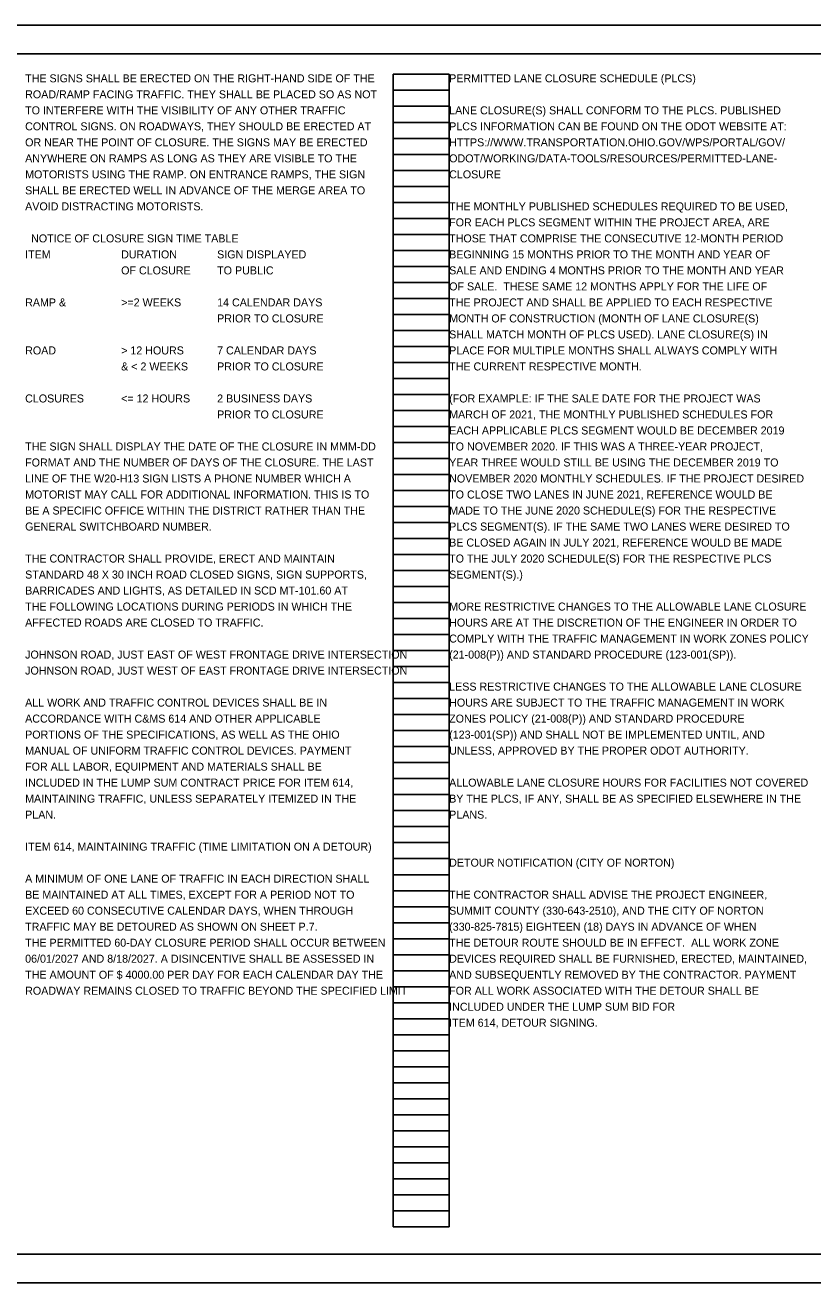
# Model space of a CAD drawing. Extents: x -9.9 to 34, y 0 to 22.
# Drawn here: x 9.82 to 23.6, y 0 to 22 of the extents above; entities that cross this region are included whole.
import ezdxf

# ---------------------------------------------------------------- set-up
doc = ezdxf.new("R2010")
doc.units = 0
for name, color, linetype in [('SH_Border', 7, 'Continuous'), ('SH_Cut_Line', 7, 'Continuous'), ('SH_Data', 7, 'Continuous'), ('SH_Text', 7, 'Continuous')]:
    doc.layers.add(name, color=color, linetype=linetype)

msp = doc.modelspace()

# ---------------------------------------------------------------- linework, layer by layer
at = {"layer": 'SH_Border'}
msp.add_lwpolyline([(1.5, 21.5), (33.5, 21.5), (33.5, 0.5), (1.5, 0.5)], close=True, dxfattribs=at)
at = {"layer": 'SH_Cut_Line'}
msp.add_lwpolyline([(0, 0), (34, 0), (34, 22), (0, 22)], close=True, dxfattribs=at)
at = {"layer": 'SH_Data'}
for p, q in [((16.26, 0.98), (16.26, 21.14)), ((16.26, 21.14), (17.24, 21.14)), ((17.24, 0.98), (17.24, 21.14)), ((16.26, 20.86), (17.24, 20.86)), ((16.26, 20.58), (17.24, 20.58)), ((16.26, 20.3), (17.24, 20.3)), ((16.26, 20.02), (17.24, 20.02)), ((16.26, 19.74), (17.24, 19.74)), ((16.26, 19.46), (17.24, 19.46)), ((16.26, 19.18), (17.24, 19.18)), ((16.26, 18.9), (17.24, 18.9)), ((16.26, 18.62), (17.24, 18.62)), ((16.26, 18.34), (17.24, 18.34)), ((16.26, 18.06), (17.24, 18.06)), ((16.26, 17.78), (17.24, 17.78)), ((16.26, 17.5), (17.24, 17.5)), ((16.26, 17.22), (17.24, 17.22)), ((16.26, 16.94), (17.24, 16.94)), ((16.26, 16.66), (17.24, 16.66)), ((16.26, 16.38), (17.24, 16.38)), ((16.26, 16.1), (17.24, 16.1)), ((16.26, 15.82), (17.24, 15.82)), ((16.26, 15.54), (17.24, 15.54)), ((16.26, 15.26), (17.24, 15.26)), ((16.26, 14.98), (17.24, 14.98)), ((16.26, 14.7), (17.24, 14.7)), ((16.26, 14.42), (17.24, 14.42)), ((16.26, 14.14), (17.24, 14.14)), ((16.26, 13.86), (17.24, 13.86)), ((16.26, 13.58), (17.24, 13.58)), ((16.26, 13.3), (17.24, 13.3)), ((16.26, 13.02), (17.24, 13.02)), ((16.26, 12.74), (17.24, 12.74)), ((16.26, 12.46), (17.24, 12.46)), ((16.26, 12.18), (17.24, 12.18)), ((16.26, 11.9), (17.24, 11.9)), ((16.26, 11.62), (17.24, 11.62)), ((16.26, 11.34), (17.24, 11.34)), ((16.26, 11.06), (17.24, 11.06)), ((16.26, 10.78), (17.24, 10.78)), ((16.26, 10.5), (17.24, 10.5)), ((16.26, 10.22), (17.24, 10.22)), ((16.26, 9.94), (17.24, 9.94)), ((16.26, 9.66), (17.24, 9.66)), ((16.26, 9.38), (17.24, 9.38)), ((16.26, 9.1), (17.24, 9.1)), ((16.26, 8.82), (17.24, 8.82)), ((16.26, 8.54), (17.24, 8.54)), ((16.26, 8.26), (17.24, 8.26)), ((16.26, 7.98), (17.24, 7.98)), ((16.26, 7.7), (17.24, 7.7)), ((16.26, 7.42), (17.24, 7.42)), ((16.26, 7.14), (17.24, 7.14)), ((16.26, 6.86), (17.24, 6.86)), ((16.26, 6.58), (17.24, 6.58)), ((16.26, 6.3), (17.24, 6.3)), ((16.26, 6.02), (17.24, 6.02)), ((16.26, 5.74), (17.24, 5.74)), ((16.26, 5.46), (17.24, 5.46)), ((16.26, 5.18), (17.24, 5.18)), ((16.26, 4.9), (17.24, 4.9)), ((16.26, 4.62), (17.24, 4.62)), ((16.26, 4.34), (17.24, 4.34)), ((16.26, 4.06), (17.24, 4.06)), ((16.26, 3.78), (17.24, 3.78)), ((16.26, 3.5), (17.24, 3.5)), ((16.26, 3.22), (17.24, 3.22)), ((16.26, 2.94), (17.24, 2.94)), ((16.26, 2.66), (17.24, 2.66)), ((16.26, 2.38), (17.24, 2.38)), ((16.26, 2.1), (17.24, 2.1)), ((16.26, 1.82), (17.24, 1.82)), ((16.26, 1.54), (17.24, 1.54)), ((16.26, 1.26), (17.24, 1.26)), ((16.26, 0.98), (17.24, 0.98))]:
    msp.add_line(p, q, dxfattribs=at)

# ---------------------------------------------------------------- texts
at = {"layer": 'SH_Text'}
for s, p in [('THE SIGNS SHALL BE ERECTED ON THE RIGHT-HAND SIDE OF THE', (9.82, 21)), ('PERMITTED LANE CLOSURE SCHEDULE (PLCS)', (17.24, 21)), ('ROAD/RAMP FACING TRAFFIC. THEY SHALL BE PLACED SO AS NOT', (9.82, 20.72)), ('TO INTERFERE WITH THE VISIBILITY OF ANY OTHER TRAFFIC', (9.82, 20.44)), ('LANE CLOSURE(S) SHALL CONFORM TO THE PLCS. PUBLISHED', (17.24, 20.44)), ('CONTROL SIGNS. ON ROADWAYS, THEY SHOULD BE ERECTED AT', (9.82, 20.16)), ('PLCS INFORMATION CAN BE FOUND ON THE ODOT WEBSITE AT:', (17.24, 20.16)), ('OR NEAR THE POINT OF CLOSURE. THE SIGNS MAY BE ERECTED', (9.82, 19.88)), ('HTTPS://WWW.TRANSPORTATION.OHIO.GOV/WPS/PORTAL/GOV/', (17.24, 19.88)), ('ANYWHERE ON RAMPS AS LONG AS THEY ARE VISIBLE TO THE', (9.82, 19.6)), ('ODOT/WORKING/DATA-TOOLS/RESOURCES/PERMITTED-LANE-', (17.24, 19.6)), ('MOTORISTS USING THE RAMP. ON ENTRANCE RAMPS, THE SIGN', (9.82, 19.32)), ('CLOSURE', (17.24, 19.32)), ('SHALL BE ERECTED WELL IN ADVANCE OF THE MERGE AREA TO', (9.82, 19.04)), ('AVOID DISTRACTING MOTORISTS.', (9.82, 18.76)), ('THE MONTHLY PUBLISHED SCHEDULES REQUIRED TO BE USED,', (17.24, 18.76)), ('FOR EACH PLCS SEGMENT WITHIN THE PROJECT AREA, ARE', (17.24, 18.48)), ('  NOTICE OF CLOSURE SIGN TIME TABLE', (9.82, 18.2)), ('THOSE THAT COMPRISE THE CONSECUTIVE 12-MONTH PERIOD', (17.24, 18.2)), ('ITEM', (9.82, 17.92)), ('DURATION ', (11.5, 17.92)), ('SIGN DISPLAYED', (13.18, 17.92)), ('BEGINNING 15 MONTHS PRIOR TO THE MONTH AND YEAR OF', (17.24, 17.92)), ('OF CLOSURE', (11.5, 17.64)), ('TO PUBLIC', (13.18, 17.64)), ('SALE AND ENDING 4 MONTHS PRIOR TO THE MONTH AND YEAR', (17.24, 17.64)), ('OF SALE.  THESE SAME 12 MONTHS APPLY FOR THE LIFE OF', (17.24, 17.36)), ('RAMP &', (9.82, 17.08)), ('>=2 WEEKS', (11.5, 17.08)), ('14 CALENDAR DAYS', (13.18, 17.08)), ('THE PROJECT AND SHALL BE APPLIED TO EACH RESPECTIVE', (17.24, 17.08)), ('PRIOR TO CLOSURE', (13.18, 16.8)), ('MONTH OF CONSTRUCTION (MONTH OF LANE CLOSURE(S)', (17.24, 16.8)), ('SHALL MATCH MONTH OF PLCS USED). LANE CLOSURE(S) IN', (17.24, 16.52)), ('ROAD', (9.82, 16.24)), ('> 12 HOURS', (11.5, 16.24)), ('7 CALENDAR DAYS', (13.18, 16.24)), ('PLACE FOR MULTIPLE MONTHS SHALL ALWAYS COMPLY WITH', (17.24, 16.24)), ('& < 2 WEEKS', (11.5, 15.96)), ('PRIOR TO CLOSURE', (13.18, 15.96)), ('THE CURRENT RESPECTIVE MONTH.', (17.24, 15.96)), ('CLOSURES', (9.82, 15.4)), ('<= 12 HOURS', (11.5, 15.4)), ('2 BUSINESS DAYS', (13.18, 15.4)), ('(FOR EXAMPLE: IF THE SALE DATE FOR THE PROJECT WAS', (17.24, 15.4)), ('PRIOR TO CLOSURE', (13.18, 15.12)), ('MARCH OF 2021, THE MONTHLY PUBLISHED SCHEDULES FOR', (17.24, 15.12)), ('EACH APPLICABLE PLCS SEGMENT WOULD BE DECEMBER 2019', (17.24, 14.84)), ('THE SIGN SHALL DISPLAY THE DATE OF THE CLOSURE IN MMM-DD', (9.82, 14.56)), ('TO NOVEMBER 2020. IF THIS WAS A THREE-YEAR PROJECT,', (17.24, 14.56)), ('FORMAT AND THE NUMBER OF DAYS OF THE CLOSURE. THE LAST', (9.82, 14.28)), ('YEAR THREE WOULD STILL BE USING THE DECEMBER 2019 TO', (17.24, 14.28)), ('LINE OF THE W20-H13 SIGN LISTS A PHONE NUMBER WHICH A', (9.82, 14)), ('NOVEMBER 2020 MONTHLY SCHEDULES. IF THE PROJECT DESIRED', (17.24, 14)), ('MOTORIST MAY CALL FOR ADDITIONAL INFORMATION. THIS IS TO', (9.82, 13.72)), ('TO CLOSE TWO LANES IN JUNE 2021, REFERENCE WOULD BE', (17.24, 13.72)), ('BE A SPECIFIC OFFICE WITHIN THE DISTRICT RATHER THAN THE', (9.82, 13.44)), ('MADE TO THE JUNE 2020 SCHEDULE(S) FOR THE RESPECTIVE', (17.24, 13.44)), ('GENERAL SWITCHBOARD NUMBER.', (9.82, 13.16)), ('PLCS SEGMENT(S). IF THE SAME TWO LANES WERE DESIRED TO', (17.24, 13.16)), ('BE CLOSED AGAIN IN JULY 2021, REFERENCE WOULD BE MADE', (17.24, 12.88)), ('THE CONTRACTOR SHALL PROVIDE, ERECT AND MAINTAIN', (9.82, 12.6)), ('TO THE JULY 2020 SCHEDULE(S) FOR THE RESPECTIVE PLCS', (17.24, 12.6)), ('STANDARD 48 X 30 INCH ROAD CLOSED SIGNS, SIGN SUPPORTS,', (9.82, 12.32)), ('SEGMENT(S).)', (17.24, 12.32)), ('BARRICADES AND LIGHTS, AS DETAILED IN SCD MT-101.60 AT', (9.82, 12.04)), ('THE FOLLOWING LOCATIONS DURING PERIODS IN WHICH THE', (9.82, 11.76)), ('MORE RESTRICTIVE CHANGES TO THE ALLOWABLE LANE CLOSURE', (17.24, 11.76)), ('AFFECTED ROADS ARE CLOSED TO TRAFFIC.', (9.82, 11.48)), ('HOURS ARE AT THE DISCRETION OF THE ENGINEER IN ORDER TO', (17.24, 11.48)), ('COMPLY WITH THE TRAFFIC MANAGEMENT IN WORK ZONES POLICY', (17.24, 11.2)), ('JOHNSON ROAD, JUST EAST OF WEST FRONTAGE DRIVE INTERSECTION', (9.82, 10.92)), ('(21-008(P)) AND STANDARD PROCEDURE (123-001(SP)).', (17.24, 10.92)), ('JOHNSON ROAD, JUST WEST OF EAST FRONTAGE DRIVE INTERSECTION', (9.82, 10.64)), ('LESS RESTRICTIVE CHANGES TO THE ALLOWABLE LANE CLOSURE', (17.24, 10.36)), ('ALL WORK AND TRAFFIC CONTROL DEVICES SHALL BE IN', (9.82, 10.08)), ('HOURS ARE SUBJECT TO THE TRAFFIC MANAGEMENT IN WORK', (17.24, 10.08)), ('ACCORDANCE WITH C&MS 614 AND OTHER APPLICABLE', (9.82, 9.8)), ('ZONES POLICY (21-008(P)) AND STANDARD PROCEDURE', (17.24, 9.8)), ('PORTIONS OF THE SPECIFICATIONS, AS WELL AS THE OHIO', (9.82, 9.52)), ('(123-001(SP)) AND SHALL NOT BE IMPLEMENTED UNTIL, AND', (17.24, 9.52)), ('MANUAL OF UNIFORM TRAFFIC CONTROL DEVICES. PAYMENT', (9.82, 9.24)), ('UNLESS, APPROVED BY THE PROPER ODOT AUTHORITY.', (17.24, 9.24)), ('FOR ALL LABOR, EQUIPMENT AND MATERIALS SHALL BE', (9.82, 8.96)), ('INCLUDED IN THE LUMP SUM CONTRACT PRICE FOR ITEM 614,', (9.82, 8.68)), ('ALLOWABLE LANE CLOSURE HOURS FOR FACILITIES NOT COVERED', (17.24, 8.68)), ('MAINTAINING TRAFFIC, UNLESS SEPARATELY ITEMIZED IN THE', (9.82, 8.4)), ('BY THE PLCS, IF ANY, SHALL BE AS SPECIFIED ELSEWHERE IN THE', (17.24, 8.4)), ('PLAN.', (9.82, 8.12)), ('PLANS.', (17.24, 8.12)), ('ITEM 614, MAINTAINING TRAFFIC (TIME LIMITATION ON A DETOUR)', (9.82, 7.56)), ('DETOUR NOTIFICATION (CITY OF NORTON)', (17.24, 7.28)), ('A MINIMUM OF ONE LANE OF TRAFFIC IN EACH DIRECTION SHALL', (9.82, 7)), ('BE MAINTAINED AT ALL TIMES, EXCEPT FOR A PERIOD NOT TO ', (9.82, 6.72)), ('THE CONTRACTOR SHALL ADVISE THE PROJECT ENGINEER,', (17.24, 6.72)), ('EXCEED 60 CONSECUTIVE CALENDAR DAYS, WHEN THROUGH', (9.82, 6.44)), ('SUMMIT COUNTY (330-643-2510), AND THE CITY OF NORTON', (17.24, 6.44)), ('TRAFFIC MAY BE DETOURED AS SHOWN ON SHEET P.7. ', (9.82, 6.16)), ('(330-825-7815) EIGHTEEN (18) DAYS IN ADVANCE OF WHEN', (17.24, 6.16)), ('THE PERMITTED 60-DAY CLOSURE PERIOD SHALL OCCUR BETWEEN ', (9.82, 5.88)), ('THE DETOUR ROUTE SHOULD BE IN EFFECT.  ALL WORK ZONE ', (17.24, 5.88)), ('06/01/2027 AND 8/18/2027. A DISINCENTIVE SHALL BE ASSESSED IN', (9.82, 5.6)), ('DEVICES REQUIRED SHALL BE FURNISHED, ERECTED, MAINTAINED, ', (17.24, 5.6)), ('THE AMOUNT OF $ 4000.00 PER DAY FOR EACH CALENDAR DAY THE ', (9.82, 5.32)), ('AND SUBSEQUENTLY REMOVED BY THE CONTRACTOR. PAYMENT ', (17.24, 5.32)), ('ROADWAY REMAINS CLOSED TO TRAFFIC BEYOND THE SPECIFIED LIMIT', (9.82, 5.04)), ('FOR ALL WORK ASSOCIATED WITH THE DETOUR SHALL BE ', (17.24, 5.04)), ('INCLUDED UNDER THE LUMP SUM BID FOR ', (17.24, 4.76)), ('ITEM 614, DETOUR SIGNING.', (17.24, 4.48))]:
    msp.add_text(s, height=0.14, dxfattribs=at).set_placement(p)

doc.saveas('drawing.dxf')
